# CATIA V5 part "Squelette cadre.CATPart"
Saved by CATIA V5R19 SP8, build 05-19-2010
Part number: Squelette cadre
Publications: "Droite AB (cadre)", "Plan.2", "Plan.4"
Bounding box of the stored display mesh (mm): x 0 to 39, y 0 to 68, z 0 to 0
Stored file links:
  G:\EU_thinkMotion\CFAO_2010\MMS_groupe3\MMS_groupe3\A reprendre\lpastor\lpastor\Squelette cadre.CATPart
  C:\Users\Loïc\Documents\IFMA\Cours 2A\CFAO\Thinkmotion\Fourche avant.CATProduct
  G:\EU_thinkMotion\CFAO_2010\MMS_groupe3\MMS_groupe3\A reprendre\lpastor\lpastor\Squelette.CATProduct
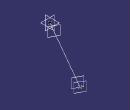
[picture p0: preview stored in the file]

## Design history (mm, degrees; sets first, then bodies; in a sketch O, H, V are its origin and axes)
Set1
  Point1 "A": linked copy from another document
  Point2 "B": linked copy from another document
Set2 "Set géométrique cadre"
  Line1 "Droite AB (cadre)": type PtPt, FirstPoint Point1, SecondPoint Point2
  Plane1: type Normal, Curve Line1, RefPoint Point1
  Plane2: type Offset, RefPlane Plane1, Offset 6
  Plane3: type Normal, Curve Line1, RefPoint Point2
  Plane4: type Offset, RefPlane Plane3, Offset 10, reversed
Body1 (main body)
